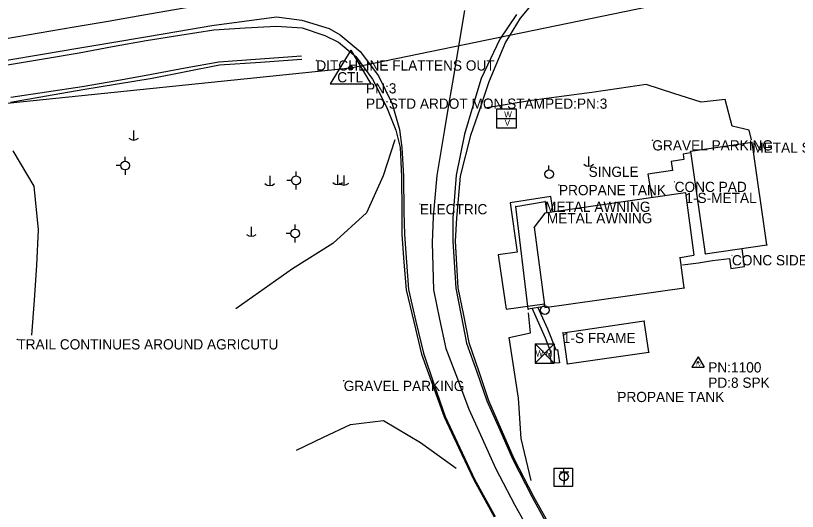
# Model space of a CAD drawing. Extents: x 1734049 to 1769984, y 344166 to 379510.
# Drawn here: x 1735978.3 to 1736361, y 378046.1 to 378288.8 of the extents above; entities that cross this region are included whole.
import ezdxf

# ---------------------------------------------------------------- set-up
doc = ezdxf.new("R2010")
doc.units = 0
for name, color, linetype in [('S_BASELINE', 7, 'Continuous'), ('S_BUILDING', 7, 'Continuous'), ('S_BUILDING_ANNOT', 7, 'Continuous'), ('S_DITCHLINE', 7, 'Continuous'), ('S_EDGE_CONCRETE', 7, 'Continuous'), ('S_EDGE_PAVEMENT', 7, 'Continuous'), ('S_ELECTRIC_UTILITIES_ANNOT', 7, 'Continuous'), ('S_MISC_STRUCTURES', 7, 'Continuous'), ('S_MISC_STRUCTURES_ANNOT', 7, 'Continuous'), ('S_MSC_PT_SYM', 7, 'Continuous'), ('S_PARKING', 7, 'Continuous'), ('S_PAVEMENT_CROWN', 7, 'Continuous'), ('S_PRIMARY_CTL', 7, 'Continuous'), ('S_PRIMARY_CTL_ANNOT', 7, 'Continuous'), ('S_SECONDARY_CTL', 7, 'Continuous'), ('S_SECONDARY_CTL_ANNOT', 7, 'Continuous'), ('S_SHOULDER', 7, 'Continuous'), ('S_SIDEWALK', 7, 'Continuous'), ('S_STR_PT_SYM', 7, 'Continuous'), ('S_SURVEY_TEXT_ANNOT', 7, 'Continuous'), ('S_TELEPHONE_UTILITIES', 7, 'Continuous'), ('S_TRAILS', 7, 'Continuous'), ('S_UTILITY_POLE', 7, 'Continuous'), ('S_UTILITY_POLE_ANNOT', 7, 'Continuous'), ('S_UTL_PT_SYM', 7, 'Continuous'), ('S_WATER_UTILITIES', 7, 'Continuous')]:
    doc.layers.add(name, color=color, linetype=linetype)

msp = doc.modelspace()

# ---------------------------------------------------------------- linework, layer by layer
at = {"layer": 'S_BASELINE'}
for p, q in [((1736142.34, 378263.18), (1737017.96, 378443.92)), ((1735254.82, 378172.19), (1736142.34, 378263.18))]:
    msp.add_line(p, q, dxfattribs=at)
at = {"layer": 'S_BUILDING'}
for p, q in [((1736338.93, 378226.67), (1736308.67, 378222.34)), ((1736346.14, 378176.51), (1736338.93, 378226.67)), ((1736308.67, 378222.34), (1736315.95, 378172.26)), ((1736306.18, 378202.05), (1736237.42, 378192.05)), ((1736306.18, 378202.05), (1736310.35, 378171.51)), ((1736237.42, 378192.05), (1736232.21, 378185.2)), ((1736232.21, 378185.2), (1736237.39, 378145.92)), ((1736315.95, 378172.26), (1736346.14, 378176.51)), ((1736303.69, 378170.42), (1736310.35, 378171.51)), ((1736305.63, 378155.47), (1736303.69, 378170.42)), ((1736237.39, 378145.92), (1736305.63, 378155.47)), ((1736246.16, 378133.51), (1736286.06, 378139.35)), ((1736288.26, 378124), (1736286.06, 378139.35)), ((1736246.16, 378133.51), (1736248.34, 378118.31)), ((1736248.34, 378118.31), (1736288.26, 378124))]:
    msp.add_line(p, q, dxfattribs=at)
at = {"layer": 'S_DITCHLINE'}
for points in [[(1735975.88, 378248.86), (1735993.41, 378251.45), (1736010.93, 378254.04), (1736027.87, 378257.07), (1736044.82, 378260.09), (1736061.29, 378263.15), (1736077.77, 378266.2), (1736098, 378267.64), (1736118.23, 378269.07)], [(1735975.71, 378246.48), (1735993.45, 378249.51), (1736011.2, 378252.54), (1736028.2, 378255.39), (1736045.2, 378258.23), (1736061.62, 378261.44), (1736078.04, 378264.65), (1736098.25, 378266.02), (1736118.46, 378267.39)]]:
    msp.add_lwpolyline(points, dxfattribs=at)
at = {"layer": 'S_EDGE_CONCRETE'}
for points in [[(1736308.74, 378221.56), (1736305.09, 378220.96), (1736305.4, 378218.37), (1736299.23, 378217.38), (1736299.85, 378212.92), (1736287.89, 378211.16), (1736289.7, 378199.79)], [(1736241.49, 378192.56), (1736240.33, 378200.21), (1736220.45, 378197.2), (1736223.91, 378173), (1736214.53, 378171.63), (1736216.48, 378158.37), (1736218.42, 378145.1), (1736237.2, 378147.63)], [(1736304.77, 378166.82), (1736312.63, 378167.8), (1736319.39, 378168.9), (1736327.72, 378169.83), (1736328.38, 378165.03), (1736335.14, 378166.02), (1736334.04, 378174.63)]]:
    msp.add_lwpolyline(points, dxfattribs=at)
at = {"layer": 'S_EDGE_PAVEMENT'}
for points in [[(1735973.99, 378267.01), (1735991.4, 378269.91), (1736008.81, 378272.82), (1736025.37, 378275.61), (1736041.94, 378278.4), (1736058.17, 378281.19), (1736074.41, 378283.99), (1736090.2, 378286.05), (1736105.99, 378288.1), (1736118.47, 378286.59), (1736131.75, 378282.5), (1736137.26, 378279.35), (1736146.95, 378271.18), (1736155.9, 378259.37), (1736162.62, 378245.54), (1736166.24, 378233.01), (1736167.45, 378224.23), (1736168.15, 378210.13), (1736168.42, 378192.79), (1736168.69, 378181.68), (1736169.64, 378168.17), (1736170.58, 378154.65), (1736174.3, 378139.09), (1736178.03, 378123.53), (1736183.28, 378108.06), (1736188.52, 378092.59), (1736195.74, 378077.22), (1736202.97, 378061.85), (1736212.99, 378043.66)], [(1736223.46, 378289.4), (1736215.41, 378277.17), (1736206.24, 378258.04), (1736202.16, 378244.42), (1736198.09, 378230.81), (1736193.96, 378210.64), (1736192.28, 378189.82), (1736192.33, 378178.42), (1736193.84, 378155.46), (1736196.45, 378142), (1736199.07, 378128.53), (1736204.06, 378114.37), (1736209.06, 378100.22), (1736215.32, 378086.02), (1736221.58, 378071.82), (1736231.18, 378053.03), (1736239.54, 378037.86)]]:
    msp.add_lwpolyline(points, dxfattribs=at)
at = {"layer": 'S_MISC_STRUCTURES'}
for p, q in [((1736223.11, 378195.37), (1736237.47, 378197.72)), ((1736237.47, 378197.72), (1736238.38, 378192.12)), ((1736229.29, 378145.05), (1736223.11, 378195.37)), ((1736237.23, 378146.37), (1736229.29, 378145.05))]:
    msp.add_line(p, q, dxfattribs=at)
at = {"layer": 'S_MSC_PT_SYM'}
for points in [[(1736125.52, 378266.88), (1736125.52, 378266.93), (1736125.52, 378266.88), (1736125.47, 378266.88), (1736125.52, 378266.88), (1736125.52, 378266.83), (1736125.52, 378266.88), (1736125.57, 378266.88)], [(1736290.02, 378227.78), (1736290.02, 378227.83), (1736290.02, 378227.78), (1736289.97, 378227.78), (1736290.02, 378227.78), (1736290.02, 378227.73), (1736290.02, 378227.78), (1736290.07, 378227.78)], [(1736300.95, 378207.45), (1736300.95, 378207.5), (1736300.95, 378207.45), (1736300.9, 378207.45), (1736300.95, 378207.45), (1736300.95, 378207.4), (1736300.95, 378207.45), (1736301, 378207.45)], [(1736244.29, 378205.88), (1736244.29, 378205.93), (1736244.29, 378205.88), (1736244.24, 378205.88), (1736244.29, 378205.88), (1736244.29, 378205.83), (1736244.29, 378205.88), (1736244.34, 378205.88)], [(1736237.47, 378197.72), (1736237.47, 378197.77), (1736237.47, 378197.72), (1736237.42, 378197.72), (1736237.47, 378197.72), (1736237.47, 378197.67), (1736237.47, 378197.72), (1736237.52, 378197.72)], [(1736223.11, 378195.37), (1736223.11, 378195.42), (1736223.11, 378195.37), (1736223.06, 378195.37), (1736223.11, 378195.37), (1736223.11, 378195.32), (1736223.11, 378195.37), (1736223.16, 378195.37)], [(1736238.38, 378192.12), (1736238.38, 378192.17), (1736238.38, 378192.12), (1736238.33, 378192.12), (1736238.38, 378192.12), (1736238.38, 378192.07), (1736238.38, 378192.12), (1736238.43, 378192.12)], [(1736329, 378171.54), (1736329, 378171.59), (1736329, 378171.54), (1736328.95, 378171.54), (1736329, 378171.54), (1736329, 378171.49), (1736329, 378171.54), (1736329.05, 378171.54)], [(1736237.23, 378146.37), (1736237.23, 378146.42), (1736237.23, 378146.37), (1736237.18, 378146.37), (1736237.23, 378146.37), (1736237.23, 378146.32), (1736237.23, 378146.37), (1736237.28, 378146.37)], [(1736229.29, 378145.05), (1736229.29, 378145.1), (1736229.29, 378145.05), (1736229.24, 378145.05), (1736229.29, 378145.05), (1736229.29, 378145), (1736229.29, 378145.05), (1736229.34, 378145.05)], [(1735979.12, 378130.38), (1735979.12, 378130.43), (1735979.12, 378130.38), (1735979.07, 378130.38), (1735979.12, 378130.38), (1735979.12, 378130.33), (1735979.12, 378130.38), (1735979.17, 378130.38)], [(1736138.93, 378110.06), (1736138.93, 378110.11), (1736138.93, 378110.06), (1736138.88, 378110.06), (1736138.93, 378110.06), (1736138.93, 378110.01), (1736138.93, 378110.06), (1736138.98, 378110.06)], [(1736272.87, 378104.64), (1736272.87, 378104.69), (1736272.87, 378104.64), (1736272.82, 378104.64), (1736272.87, 378104.64), (1736272.87, 378104.59), (1736272.87, 378104.64), (1736272.92, 378104.64)]]:
    msp.add_lwpolyline(points, dxfattribs=at)
at = {"layer": 'S_PARKING'}
for points in [[(1736338.49, 378228), (1736337.47, 378232.77), (1736329.14, 378234.68), (1736325.68, 378247.71), (1736313.94, 378246.36), (1736300.49, 378250.72), (1736287.03, 378255.07), (1736273.71, 378253.13), (1736260.38, 378251.19), (1736245.61, 378249.18), (1736230.84, 378247.18), (1736207.95, 378243.44)], [(1736163.95, 378227.99), (1736158.29, 378210.38), (1736150.01, 378192.24), (1736133.66, 378177.28), (1736113.77, 378164.86), (1736099.93, 378155.03), (1736086.1, 378145.2)], [(1736230.67, 378061.24), (1736225.8, 378081.86), (1736224.52, 378101.51), (1736222.2, 378116.39), (1736219.89, 378131.27), (1736230.31, 378133.47), (1736229.4, 378143.32)], [(1736115.73, 378076.17), (1736128.98, 378082.43), (1736142.23, 378088.69), (1736158.44, 378090.53), (1736176.48, 378079.77), (1736193.95, 378067.34)]]:
    msp.add_lwpolyline(points, dxfattribs=at)
at = {"layer": 'S_PAVEMENT_CROWN'}
for points in [[(1735972.71, 378277.41), (1735989.87, 378280.32), (1736007.03, 378283.22), (1736023.53, 378286.08), (1736040.04, 378288.94), (1736056.15, 378291.76), (1736072.26, 378294.57), (1736088.53, 378297.49), (1736104.79, 378300.41), (1736117.52, 378302.62), (1736132.36, 378305.06), (1736145.43, 378307.37), (1736158.51, 378309.67), (1736170.94, 378311.86), (1736183.36, 378314.05)], [(1736198.07, 378291.2), (1736194.77, 378271.9), (1736192.63, 378258.9), (1736190.4, 378245.95), (1736188.18, 378233), (1736184.53, 378210.55), (1736182.78, 378190.4), (1736182.3, 378177.58), (1736182.82, 378154.61), (1736185.86, 378140.25), (1736188.9, 378125.89), (1736194.56, 378111.06), (1736200.22, 378096.23), (1736206.75, 378081.73), (1736213.28, 378067.24), (1736222.68, 378049.1), (1736231.55, 378033.57)]]:
    msp.add_lwpolyline(points, dxfattribs=at)
at = {"layer": 'S_PRIMARY_CTL'}
for p, q in [((1736142.34, 378271.88), (1736132.3, 378255.37)), ((1736142.34, 378271.88), (1736152.16, 378255.37)), ((1736132.3, 378255.37), (1736152.16, 378255.37))]:
    msp.add_line(p, q, dxfattribs=at)
for radius in [1.04, 0.609, 0.344]:
    msp.add_circle((1736142.34, 378263.18), radius, dxfattribs=at)
at = {"layer": 'S_SECONDARY_CTL'}
for p, q in [((1736312.39, 378121.73), (1736309.38, 378116.78)), ((1736312.39, 378121.73), (1736315.33, 378116.78)), ((1736309.38, 378116.78), (1736315.33, 378116.78))]:
    msp.add_line(p, q, dxfattribs=at)
for radius in [0.311, 0.183, 0.103]:
    msp.add_circle((1736312.39, 378119.12), radius, dxfattribs=at)
at = {"layer": 'S_SHOULDER'}
for points in [[(1736279.34, 378321.72), (1736266.15, 378316.86), (1736253.72, 378310.6), (1736240.47, 378302.68), (1736232.75, 378296.72), (1736225.36, 378287.59), (1736218.11, 378275.78), (1736210.03, 378256.3), (1736205.5, 378243.16), (1736200.97, 378230.03), (1736195.85, 378210.27), (1736194.14, 378189.63), (1736193.54, 378178.44), (1736194.83, 378155.51), (1736197.53, 378142.13), (1736200.23, 378128.76), (1736204.99, 378114.55), (1736209.74, 378100.34), (1736215.93, 378086.21), (1736222.13, 378072.08), (1736231.88, 378053.49), (1736240.27, 378038.26)], [(1735974.31, 378264.65), (1735991.89, 378267.63), (1736009.46, 378270.62), (1736025.79, 378273.6), (1736042.12, 378276.59), (1736058.72, 378279.21), (1736075.32, 378281.83), (1736090.68, 378282.74), (1736106.03, 378283.65), (1736118.56, 378282.78), (1736129.73, 378279.1), (1736136.32, 378275.74), (1736144.92, 378268.72), (1736153.06, 378257.65), (1736159.8, 378244.14), (1736164.46, 378232.66), (1736166.51, 378224.18), (1736167.26, 378210), (1736167.34, 378192.58), (1736167.31, 378181.59), (1736168.37, 378168.07), (1736169.42, 378154.56), (1736173.18, 378138.83), (1736176.95, 378123.1), (1736182.51, 378107.73), (1736188.08, 378092.36), (1736195.32, 378077), (1736202.57, 378061.64), (1736212.65, 378043.47)]]:
    msp.add_lwpolyline(points, dxfattribs=at)
at = {"layer": 'S_SIDEWALK'}
msp.add_lwpolyline([(1736233.73, 378146.29), (1736238.72, 378135.5), (1736242.8, 378125.25), (1736243.56, 378125.43), (1736244.55, 378118.76), (1736240.62, 378118.72), (1736239.81, 378123.39), (1736240.56, 378123.65), (1736237.63, 378130.96), (1736231.24, 378145.62)], dxfattribs=at)
at = {"layer": 'S_STR_PT_SYM'}
for points in [[(1736338.93, 378226.67), (1736338.93, 378226.72), (1736338.93, 378226.67), (1736338.88, 378226.67), (1736338.93, 378226.67), (1736338.93, 378226.62), (1736338.93, 378226.67), (1736338.98, 378226.67)], [(1736338.93, 378226.67), (1736338.93, 378226.72), (1736338.93, 378226.67), (1736338.88, 378226.67), (1736338.93, 378226.67), (1736338.93, 378226.62), (1736338.93, 378226.67), (1736338.98, 378226.67)], [(1736308.67, 378222.34), (1736308.67, 378222.39), (1736308.67, 378222.34), (1736308.62, 378222.34), (1736308.67, 378222.34), (1736308.67, 378222.29), (1736308.67, 378222.34), (1736308.72, 378222.34)], [(1736306.18, 378202.05), (1736306.18, 378202.1), (1736306.18, 378202.05), (1736306.13, 378202.05), (1736306.18, 378202.05), (1736306.18, 378202), (1736306.18, 378202.05), (1736306.23, 378202.05)], [(1736306.18, 378202.05), (1736306.18, 378202.1), (1736306.18, 378202.05), (1736306.13, 378202.05), (1736306.18, 378202.05), (1736306.18, 378202), (1736306.18, 378202.05), (1736306.23, 378202.05)], [(1736237.42, 378192.05), (1736237.42, 378192.1), (1736237.42, 378192.05), (1736237.37, 378192.05), (1736237.42, 378192.05), (1736237.42, 378192), (1736237.42, 378192.05), (1736237.47, 378192.05)], [(1736232.21, 378185.2), (1736232.21, 378185.25), (1736232.21, 378185.2), (1736232.16, 378185.2), (1736232.21, 378185.2), (1736232.21, 378185.15), (1736232.21, 378185.2), (1736232.26, 378185.2)], [(1736346.14, 378176.51), (1736346.14, 378176.56), (1736346.14, 378176.51), (1736346.09, 378176.51), (1736346.14, 378176.51), (1736346.14, 378176.46), (1736346.14, 378176.51), (1736346.19, 378176.51)], [(1736346.14, 378176.51), (1736346.14, 378176.56), (1736346.14, 378176.51), (1736346.09, 378176.51), (1736346.14, 378176.51), (1736346.14, 378176.46), (1736346.14, 378176.51), (1736346.19, 378176.51)], [(1736303.69, 378170.42), (1736303.69, 378170.47), (1736303.69, 378170.42), (1736303.64, 378170.42), (1736303.69, 378170.42), (1736303.69, 378170.37), (1736303.69, 378170.42), (1736303.74, 378170.42)], [(1736310.35, 378171.51), (1736310.35, 378171.56), (1736310.35, 378171.51), (1736310.3, 378171.51), (1736310.35, 378171.51), (1736310.35, 378171.46), (1736310.35, 378171.51), (1736310.4, 378171.51)], [(1736310.35, 378171.51), (1736310.35, 378171.56), (1736310.35, 378171.51), (1736310.3, 378171.51), (1736310.35, 378171.51), (1736310.35, 378171.46), (1736310.35, 378171.51), (1736310.4, 378171.51)], [(1736315.95, 378172.26), (1736315.95, 378172.31), (1736315.95, 378172.26), (1736315.9, 378172.26), (1736315.95, 378172.26), (1736315.95, 378172.21), (1736315.95, 378172.26), (1736316, 378172.26)], [(1736305.63, 378155.47), (1736305.63, 378155.52), (1736305.63, 378155.47), (1736305.58, 378155.47), (1736305.63, 378155.47), (1736305.63, 378155.42), (1736305.63, 378155.47), (1736305.68, 378155.47)], [(1736237.39, 378145.92), (1736237.39, 378145.97), (1736237.39, 378145.92), (1736237.34, 378145.92), (1736237.39, 378145.92), (1736237.39, 378145.87), (1736237.39, 378145.92), (1736237.44, 378145.92)], [(1736286.06, 378139.35), (1736286.06, 378139.4), (1736286.06, 378139.35), (1736286.01, 378139.35), (1736286.06, 378139.35), (1736286.06, 378139.3), (1736286.06, 378139.35), (1736286.11, 378139.35)], [(1736286.06, 378139.35), (1736286.06, 378139.4), (1736286.06, 378139.35), (1736286.01, 378139.35), (1736286.06, 378139.35), (1736286.06, 378139.3), (1736286.06, 378139.35), (1736286.11, 378139.35)], [(1736246.16, 378133.51), (1736246.16, 378133.56), (1736246.16, 378133.51), (1736246.11, 378133.51), (1736246.16, 378133.51), (1736246.16, 378133.46), (1736246.16, 378133.51), (1736246.21, 378133.51)], [(1736246.16, 378133.51), (1736246.16, 378133.56), (1736246.16, 378133.51), (1736246.11, 378133.51), (1736246.16, 378133.51), (1736246.16, 378133.46), (1736246.16, 378133.51), (1736246.21, 378133.51)], [(1736288.26, 378124), (1736288.26, 378124.05), (1736288.26, 378124), (1736288.21, 378124), (1736288.26, 378124), (1736288.26, 378123.95), (1736288.26, 378124), (1736288.31, 378124)], [(1736248.34, 378118.31), (1736248.34, 378118.36), (1736248.34, 378118.31), (1736248.29, 378118.31), (1736248.34, 378118.31), (1736248.34, 378118.26), (1736248.34, 378118.31), (1736248.39, 378118.31)]]:
    msp.add_lwpolyline(points, dxfattribs=at)
at = {"layer": 'S_TELEPHONE_UTILITIES'}
msp.add_lwpolyline([(1736241.95, 378058.31), (1736241.95, 378067.31), (1736250.95, 378067.31), (1736250.95, 378058.31)], close=True, dxfattribs=at)
at = {"layer": 'S_TRAILS'}
msp.add_lwpolyline([(1735976.9, 378222.62), (1735987.21, 378205.25), (1735989.4, 378183.93), (1735988.46, 378166.7), (1735987.3, 378149.5), (1735986.13, 378132.3)], dxfattribs=at)
at = {"layer": 'S_UTILITY_POLE'}
for p, q in [((1736036.03, 378232.55), (1736036.03, 378227.82)), ((1736031.96, 378217.47), (1736031.96, 378219.72)), ((1736258.8, 378219.79), (1736258.8, 378215.06)), ((1736029.87, 378215.34), (1736027.54, 378215.34)), ((1736239.35, 378213.35), (1736239.35, 378215.46)), ((1736032.04, 378210.92), (1736032.04, 378213.25)), ((1736115.56, 378210.26), (1736115.56, 378212.51)), ((1736135.85, 378210.83), (1736135.85, 378206.1)), ((1736102.67, 378210.31), (1736102.67, 378205.59)), ((1736113.47, 378208.13), (1736111.14, 378208.13)), ((1736138.97, 378210.57), (1736138.97, 378205.85)), ((1736115.64, 378203.71), (1736115.64, 378206.04)), ((1736093.67, 378185.46), (1736093.67, 378180.73)), ((1736115.11, 378184.31), (1736115.11, 378186.56)), ((1736113.02, 378182.18), (1736110.69, 378182.18)), ((1736115.19, 378177.76), (1736115.19, 378180.09)), ((1736237.29, 378146.8), (1736237.29, 378148.91)), ((1736246.63, 378065.35), (1736246.63, 378067.46)), ((1736246.67, 378065.28), (1736246.67, 378067.4)), ((1736246.67, 378061.06), (1736246.67, 378059))]:
    msp.add_line(p, q, dxfattribs=at)
for centre, radius in [((1736031.96, 378215.36), 2.13), ((1736239.47, 378211.21), 2.13), ((1736115.56, 378208.15), 2.13), ((1736115.11, 378182.2), 2.13), ((1736237.41, 378144.66), 2.13), ((1736246.69, 378063.2), 2.11), ((1736246.76, 378063.21), 2.13)]:
    msp.add_circle(centre, radius, dxfattribs=at)
for centre in [(1736036.1, 378231.24), (1736258.86, 378218.49), (1736135.92, 378209.52), (1736102.73, 378209.01), (1736139.03, 378209.27), (1736093.73, 378184.16)]:
    msp.add_arc(centre, 3.41, 226.3972, 313.6028, dxfattribs=at)
at = {"layer": 'S_UTL_PT_SYM'}
msp.add_lwpolyline([(1736176.17, 378196.53), (1736176.17, 378196.58), (1736176.17, 378196.53), (1736176.12, 378196.53), (1736176.17, 378196.53), (1736176.17, 378196.48), (1736176.17, 378196.53), (1736176.22, 378196.53)], dxfattribs=at)
at = {"layer": 'S_WATER_UTILITIES'}
for p, q in [((1736213.93, 378243.07), (1736223.34, 378243.07)), ((1736213.93, 378233.65), (1736213.93, 378243.07)), ((1736223.34, 378243.07), (1736223.34, 378233.65)), ((1736213.93, 378238.38), (1736223.34, 378238.38)), ((1736223.34, 378233.65), (1736213.93, 378233.65)), ((1736232.67, 378128.14), (1736242.01, 378128.14)), ((1736232.67, 378128.14), (1736232.67, 378118.64)), ((1736232.67, 378128.14), (1736242.01, 378118.64)), ((1736242.01, 378128.14), (1736232.67, 378118.64)), ((1736242.01, 378128.14), (1736242.01, 378118.64)), ((1736232.67, 378118.64), (1736242.01, 378118.64))]:
    msp.add_line(p, q, dxfattribs=at)

# ---------------------------------------------------------------- texts
at = {"layer": 'S_BUILDING_ANNOT'}
for s, p in [('METAL SHOP BUILDING', (1736338.93, 378221.67)), ('METAL SHOP BUILDING', (1736338.93, 378221.67)), ('1-S-METAL', (1736306.18, 378197.05)), ('1-S-METAL', (1736306.18, 378197.05)), ('1-S FRAME', (1736246.16, 378128.51)), ('1-S FRAME', (1736246.16, 378128.51))]:
    msp.add_text(s, height=5, dxfattribs=at).set_placement(p)
at = {"layer": 'S_ELECTRIC_UTILITIES_ANNOT'}
msp.add_text('ELECTRIC', height=5, dxfattribs=at).set_placement((1736176.17, 378191.53))
at = {"layer": 'S_MISC_STRUCTURES_ANNOT'}
for s, p in [('PROPANE TANK', (1736244.29, 378200.88)), ('METAL AWNING', (1736237.47, 378192.72)), ('METAL AWNING', (1736238.38, 378187.12)), ('PROPANE TANK', (1736272.87, 378099.64))]:
    msp.add_text(s, height=5, dxfattribs=at).set_placement(p)
at = {"layer": 'S_PRIMARY_CTL'}
msp.add_text('CTL', height=5, rotation=360, dxfattribs=at).set_placement((1736135.75, 378256.1))
at = {"layer": 'S_PRIMARY_CTL_ANNOT'}
for s, p in [('PN:3', (1736149.84, 378250.68)), ('PD:STD ARDOT MON STAMPED:PN:3', (1736149.84, 378243.18))]:
    msp.add_text(s, height=5, dxfattribs=at).set_placement(p)
at = {"layer": 'S_SECONDARY_CTL'}
msp.add_text('TV', height=1.5, rotation=360, dxfattribs=at).set_placement((1736311.18, 378117.11))
at = {"layer": 'S_SECONDARY_CTL_ANNOT'}
for s, p in [('PN:1100', (1736317.39, 378114.12)), ('PD:8 SPK', (1736317.39, 378106.62))]:
    msp.add_text(s, height=5, dxfattribs=at).set_placement(p)
at = {"layer": 'S_SURVEY_TEXT_ANNOT'}
for s, p in [('DITCHLINE FLATTENS OUT', (1736125.52, 378261.88)), ('GRAVEL PARKING', (1736290.02, 378222.78)), ('CONC PAD', (1736300.95, 378202.45)), ('CONC SIDEWALK', (1736329, 378166.54)), ('TRAIL CONTINUES AROUND AGRICUTU', (1735979.12, 378125.38)), ('GRAVEL PARKING', (1736138.93, 378105.06))]:
    msp.add_text(s, height=5, dxfattribs=at).set_placement(p)
at = {"layer": 'S_TELEPHONE_UTILITIES'}
msp.add_text('T', height=6, rotation=360, dxfattribs=at).set_placement((1736244.51, 378059.81))
at = {"layer": 'S_UTILITY_POLE_ANNOT'}
msp.add_text('SINGLE', height=5, dxfattribs=at).set_placement((1736258.81, 378209.84))
at = {"layer": 'S_WATER_UTILITIES'}
for s, p in [('W', (1736217.48, 378238.91)), ('V', (1736217.71, 378234.85)), ('W M', (1736232.87, 378121.9))]:
    msp.add_text(s, height=3, rotation=360, dxfattribs=at).set_placement(p)

doc.saveas('drawing.dxf')
